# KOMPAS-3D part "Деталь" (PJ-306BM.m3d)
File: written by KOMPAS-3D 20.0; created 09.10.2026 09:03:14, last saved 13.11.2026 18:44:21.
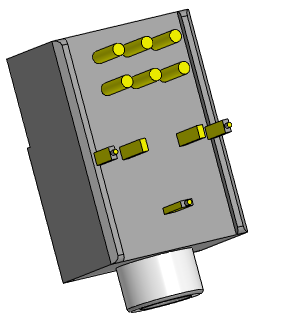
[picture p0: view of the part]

Document properties: Полное имя файла: D:\myProjects\Progect_esp32\box_compas\разъемы\PJ-306BM.m3d

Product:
- Part/product: Деталь
    Масса: 0.0145552

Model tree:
1. Эскиз:1
2. Элемент выдавливания:1
     Расстояние 1 = 17.5
3. Фаска:1  (with: Элемент выдавливания:1)
     Угол = 45; Длина 1 = 0.5; Длина 2 = 0.5
4. Эскиз:2  (with: Элемент выдавливания:1)
5. Элемент выдавливания:2
     Расстояние 2 = 17.5
6. Эскиз:3  (with: Элемент выдавливания:1)
7. Элемент выдавливания:3
     Расстояние 1 = 3.5
8. Скругление:1  (with: Элемент выдавливания:3, Элемент выдавливания:1)
     Радиус = 0.25
9. Эскиз:4  (with: Элемент выдавливания:2, Фаска:1)
10. Элемент выдавливания:4
     Расстояние 1 = 3.6
11. Скругление:3  (with: Элемент выдавливания:1)
     Радиус = 0.5
12. Эскиз:5  (with: Элемент выдавливания:1, Фаска:1, Элемент выдавливания:2)
13. Элемент выдавливания:5
     Расстояние 2 = 1
14. Эскиз:6  (with: Элемент выдавливания:4)
15. Элемент выдавливания:6
     Расстояние 2 = 0.5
